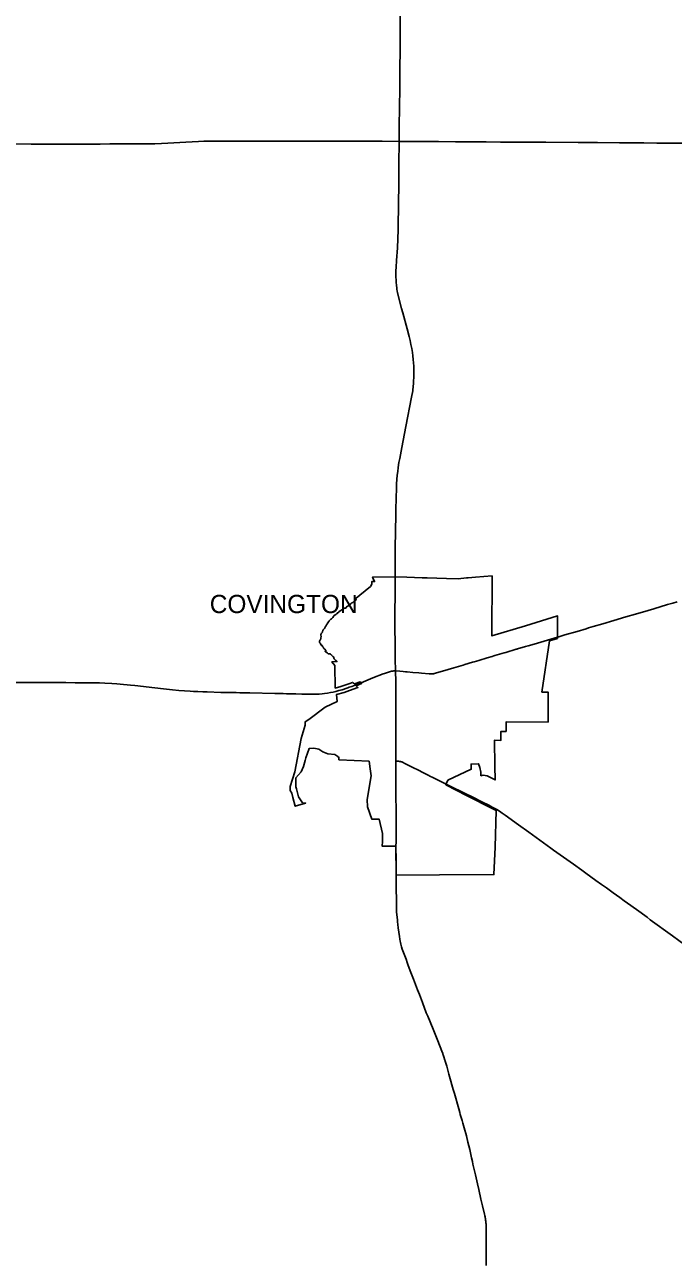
# Model space of a CAD drawing. Extents: x 0 to 34, y 0 to 22.
# Drawn here: x 4.445 to 4.73, y 17.041 to 17.585 of the extents above; entities that cross this region are included whole.
import ezdxf

# ---------------------------------------------------------------- set-up
doc = ezdxf.new("R2010")
doc.units = 0
for name, color, linetype in [('GM_X_Corporation', 7, 'Continuous'), ('GM_X_Corporation_Text', 7, 'Continuous'), ('GM_X_State_Route', 7, 'Continuous'), ('GM_X_US_Route', 7, 'Continuous')]:
    doc.layers.add(name, color=color, linetype=linetype)

msp = doc.modelspace()

# ---------------------------------------------------------------- linework, layer by layer
at = {"layer": 'GM_X_Corporation'}
msp.add_lwpolyline([(4.65031, 17.34146), (4.6502, 17.31741), (4.65023, 17.31588), (4.66507, 17.32035), (4.67914, 17.32467), (4.67914, 17.31535), (4.67907, 17.31474), (4.67565, 17.31371), (4.67228, 17.2911), (4.67507, 17.29106), (4.67497, 17.27792), (4.65652, 17.27798), (4.6565, 17.27383), (4.65425, 17.27383), (4.65423, 17.26987), (4.65139, 17.26991), (4.65139, 17.26991), (4.65158, 17.25847), (4.6517, 17.25246), (4.64813, 17.25421), (4.64639, 17.25453), (4.64542, 17.25427), (4.64538, 17.25584), (4.64487, 17.25795), (4.64442, 17.25955), (4.64106, 17.25939), (4.64115, 17.25716), (4.63092, 17.25232), (4.63009, 17.25066), (4.62993, 17.25032), (4.63944, 17.24537), (4.65036, 17.2399), (4.6521, 17.23892), (4.65169, 17.2228), (4.65117, 17.21077), (4.62721, 17.21059), (4.60809, 17.21046), (4.60802, 17.22326), (4.60191, 17.22332), (4.60204, 17.22525), (4.60212, 17.22889), (4.60067, 17.23512), (4.59741, 17.23509), (4.59548, 17.24061), (4.59538, 17.24379), (4.59619, 17.24901), (4.59664, 17.2518), (4.59709, 17.25426), (4.59667, 17.25727), (4.59619, 17.26065), (4.58301, 17.26132), (4.58291, 17.2613), (4.58287, 17.26247), (4.58247, 17.26255), (4.58247, 17.2627), (4.5811, 17.26367), (4.57806, 17.26399), (4.57582, 17.26474), (4.57408, 17.26596), (4.57193, 17.26642), (4.56988, 17.26628), (4.5684, 17.26214), (4.5681, 17.26106), (4.56737, 17.2583), (4.56635, 17.25601), (4.56396, 17.25335), (4.564, 17.24934), (4.5642, 17.2485), (4.56518, 17.24498), (4.56694, 17.24238), (4.56827, 17.24221), (4.56373, 17.24086), (4.5627, 17.24466), (4.56215, 17.24665), (4.56143, 17.2478), (4.56153, 17.24961), (4.56356, 17.25607), (4.56633, 17.27066), (4.56804, 17.27661), (4.56813, 17.27807), (4.56961, 17.2791), (4.57693, 17.28444), (4.58208, 17.28697), (4.58181, 17.29), (4.5853, 17.29097), (4.58758, 17.29176), (4.59125, 17.2932), (4.59048, 17.29394), (4.59293, 17.29489), (4.59262, 17.29526), (4.5922, 17.29566), (4.58973, 17.29469), (4.58896, 17.29542), (4.58731, 17.29476), (4.58556, 17.29411), (4.58379, 17.29353), (4.58131, 17.29286), (4.58111, 17.30289), (4.57986, 17.30449), (4.58203, 17.30455), (4.58199, 17.30468), (4.58176, 17.30485), (4.5816, 17.30496), (4.5814, 17.30513), (4.58128, 17.30531), (4.5808, 17.30572), (4.58071, 17.30602), (4.58062, 17.3064), (4.58047, 17.30668), (4.58024, 17.30686), (4.5801, 17.307), (4.57986, 17.30721), (4.57968, 17.30738), (4.57961, 17.30746), (4.57952, 17.30756), (4.57915, 17.30786), (4.57892, 17.30794), (4.57844, 17.30795), (4.57828, 17.308), (4.5782, 17.30804), (4.57788, 17.30825), (4.57774, 17.30848), (4.57757, 17.30865), (4.57745, 17.30868), (4.57717, 17.30875), (4.57694, 17.3089), (4.57683, 17.30904), (4.57694, 17.30921), (4.57709, 17.30934), (4.57709, 17.30952), (4.57704, 17.30964), (4.57684, 17.30985), (4.57674, 17.31004), (4.57665, 17.31005), (4.57645, 17.3102), (4.57632, 17.31035), (4.57617, 17.3105), (4.57608, 17.31071), (4.576, 17.31088), (4.57585, 17.31113), (4.57556, 17.31146), (4.57549, 17.31162), (4.57544, 17.31184), (4.57534, 17.31192), (4.57531, 17.31185), (4.57513, 17.31184), (4.57509, 17.31184), (4.57493, 17.31208), (4.57483, 17.31227), (4.57478, 17.31241), (4.57476, 17.31261), (4.5746, 17.31266), (4.57445, 17.31281), (4.57435, 17.31304), (4.57438, 17.31321), (4.57442, 17.31369), (4.57455, 17.31387), (4.57465, 17.31407), (4.5749, 17.31446), (4.57493, 17.31479), (4.57492, 17.31492), (4.57491, 17.31501), (4.57506, 17.31568), (4.57501, 17.31613), (4.57496, 17.31659), (4.57509, 17.31681), (4.57526, 17.31709), (4.57554, 17.31737), (4.57562, 17.31758), (4.57575, 17.31793), (4.57582, 17.31806), (4.57587, 17.31823), (4.57595, 17.31852), (4.57631, 17.31889), (4.57652, 17.31907), (4.57665, 17.31936), (4.57693, 17.31969), (4.57701, 17.32), (4.57708, 17.32008), (4.57716, 17.32022), (4.57725, 17.32045), (4.57739, 17.32069), (4.57753, 17.32094), (4.5778, 17.32125), (4.57828, 17.32201), (4.5785, 17.32224), (4.57861, 17.32253), (4.57901, 17.32291), (4.57923, 17.32312), (4.5794, 17.32328), (4.57968, 17.32343), (4.57977, 17.32356), (4.58022, 17.32399), (4.5805, 17.32444), (4.5807, 17.32467), (4.58087, 17.32482), (4.58113, 17.325), (4.58132, 17.32513), (4.58155, 17.32527), (4.58168, 17.32538), (4.58184, 17.32551), (4.58205, 17.32581), (4.58224, 17.32588), (4.58235, 17.32601), (4.58274, 17.32613), (4.58291, 17.32642), (4.58308, 17.32656), (4.58381, 17.32712), (4.58416, 17.3273), (4.58455, 17.32762), (4.58459, 17.32768), (4.58489, 17.32773), (4.58491, 17.32786), (4.58508, 17.32796), (4.58538, 17.32809), (4.58549, 17.32816), (4.58575, 17.32816), (4.58592, 17.32816), (4.58622, 17.32859), (4.58638, 17.32876), (4.58702, 17.32902), (4.58704, 17.3293), (4.5876, 17.32947), (4.58784, 17.32968), (4.58809, 17.32994), (4.58835, 17.33015), (4.58857, 17.33044), (4.58906, 17.33065), (4.58928, 17.33084), (4.58975, 17.33127), (4.59025, 17.33157), (4.59054, 17.3318), (4.59057, 17.33184), (4.5906, 17.33188), (4.58985, 17.33188), (4.59676, 17.33758), (4.59738, 17.33865), (4.59737, 17.33978), (4.59863, 17.33977), (4.59772, 17.34179), (4.60764, 17.34183), (4.61286, 17.3417), (4.61954, 17.34144), (4.6218, 17.34138), (4.63027, 17.34116), (4.63536, 17.34107), (4.63901, 17.34138), (4.63985, 17.34145), (4.64309, 17.34172), (4.65032, 17.34231)], close=True, dxfattribs=at)
at = {"layer": 'GM_X_State_Route'}
for p, q in [((4.6079, 17.28364), (4.60791, 17.28838)), ((4.60796, 17.27771), (4.60795, 17.27864)), ((4.60796, 17.27353), (4.60796, 17.27771)), ((4.608, 17.26346), (4.60798, 17.26847)), ((4.60802, 17.26073), (4.608, 17.26346))]:
    msp.add_line(p, q, dxfattribs=at)
for points in [[(4.60942, 17.5337), (4.60948, 17.53955), (4.60957, 17.54946), (4.60967, 17.55621), (4.60975, 17.56296), (4.60986, 17.57658), (4.60981, 17.58954)], [(4.43714, 17.53255), (4.44753, 17.5325), (4.45243, 17.53249), (4.45728, 17.53249), (4.46045, 17.53247), (4.46435, 17.53246), (4.47384, 17.5325), (4.4779, 17.53251), (4.48212, 17.53255), (4.49177, 17.53256), (4.49673, 17.53257), (4.49926, 17.53259), (4.50183, 17.53266), (4.5048, 17.53276), (4.50769, 17.53289), (4.51559, 17.53334), (4.52117, 17.53367), (4.52348, 17.53376), (4.52612, 17.53384), (4.53255, 17.53383), (4.54289, 17.53384), (4.54758, 17.5338), (4.55518, 17.53378), (4.5585, 17.53378), (4.5681, 17.53378), (4.57896, 17.53375), (4.58365, 17.53376), (4.59694, 17.53371), (4.60195, 17.53372), (4.60942, 17.5337)], [(4.60766, 17.34183), (4.60767, 17.34214), (4.60769, 17.34242), (4.60773, 17.35329), (4.60787, 17.36314), (4.60793, 17.36795), (4.60798, 17.37106), (4.6081, 17.37702), (4.60821, 17.38055), (4.60831, 17.38279), (4.60843, 17.38473), (4.60858, 17.38666), (4.60878, 17.38834), (4.609, 17.39001), (4.60934, 17.3922), (4.60966, 17.39402), (4.61059, 17.39883), (4.61242, 17.40805), (4.61493, 17.42102), (4.61538, 17.42385), (4.61547, 17.42452), (4.61556, 17.42531), (4.61563, 17.42606), (4.61569, 17.42673), (4.61578, 17.42809), (4.61586, 17.42988), (4.61589, 17.43167), (4.61588, 17.43309), (4.61584, 17.43462), (4.61575, 17.43614), (4.61563, 17.43761), (4.61546, 17.43918), (4.61525, 17.44069), (4.61495, 17.44251), (4.61463, 17.44422), (4.61424, 17.44602), (4.61382, 17.44776), (4.61295, 17.45108), (4.61103, 17.45821), (4.61052, 17.46015), (4.60906, 17.46576), (4.60874, 17.46719), (4.60862, 17.46778), (4.60847, 17.46862), (4.60837, 17.46937), (4.60829, 17.46999), (4.60822, 17.47059), (4.60817, 17.47118), (4.60806, 17.47266), (4.60801, 17.47382), (4.608, 17.47509), (4.60803, 17.47662), (4.60811, 17.47825), (4.6083, 17.4812), (4.6087, 17.48683), (4.60891, 17.49081), (4.60901, 17.49477), (4.60905, 17.49673), (4.60907, 17.49916), (4.60914, 17.50279), (4.60917, 17.50796), (4.60922, 17.51308), (4.60929, 17.5194), (4.6093, 17.52204), (4.60932, 17.52568), (4.60941, 17.53153), (4.60942, 17.5337)], [(4.60942, 17.5337), (4.6135, 17.53369), (4.61972, 17.53362), (4.62678, 17.53357), (4.63417, 17.53353), (4.6367, 17.5335), (4.64044, 17.53348), (4.64476, 17.53345), (4.64771, 17.53344), (4.65404, 17.53339), (4.65552, 17.53338), (4.65821, 17.53336), (4.66243, 17.53335), (4.66912, 17.53331), (4.67181, 17.5333), (4.67392, 17.53329), (4.68826, 17.53319), (4.69064, 17.53319), (4.69368, 17.53317), (4.69675, 17.53315), (4.7064, 17.53306), (4.71711, 17.533), (4.7229, 17.53297), (4.72533, 17.53294), (4.72955, 17.53292), (4.73708, 17.53284)], [(4.60785, 17.30055), (4.60772, 17.30581), (4.60769, 17.30686), (4.6077, 17.31117), (4.6077, 17.31133), (4.60762, 17.31549), (4.6076, 17.31643), (4.60757, 17.31849), (4.60757, 17.32036), (4.60756, 17.32165), (4.60756, 17.32249), (4.60757, 17.32509), (4.60757, 17.3258), (4.60758, 17.32659), (4.60763, 17.33375), (4.60762, 17.33534), (4.60764, 17.34152), (4.60766, 17.34183)], [(4.60791, 17.28838), (4.60792, 17.29567), (4.60785, 17.30055)], [(4.60795, 17.27864), (4.6079, 17.28357), (4.6079, 17.28364)], [(4.60798, 17.26847), (4.60796, 17.27197), (4.60796, 17.27353)], [(4.61038, 17.26043), (4.61009, 17.26051), (4.60979, 17.26056), (4.60958, 17.2606), (4.60921, 17.26064), (4.60802, 17.26073)], [(4.60805, 17.23673), (4.60805, 17.23877), (4.60805, 17.24036), (4.60803, 17.24415), (4.60804, 17.24822), (4.60804, 17.25069), (4.60803, 17.25533), (4.60802, 17.25861), (4.60802, 17.26073)], [(4.61952, 17.25587), (4.61817, 17.25655), (4.61765, 17.25681), (4.61575, 17.25774), (4.61317, 17.25907), (4.61191, 17.25972), (4.61091, 17.26023), (4.61066, 17.26034), (4.61038, 17.26043)], [(4.62958, 17.25088), (4.62395, 17.25364), (4.62323, 17.254), (4.62215, 17.25454), (4.61952, 17.25587)], [(4.73537, 17.17967), (4.72977, 17.18376), (4.71996, 17.19085), (4.71855, 17.19194), (4.71394, 17.19529), (4.70995, 17.19814), (4.70847, 17.19924), (4.70653, 17.20061), (4.70366, 17.20266), (4.70063, 17.20485), (4.69845, 17.20643), (4.696, 17.20818), (4.69155, 17.21138), (4.68986, 17.21263), (4.68612, 17.21529), (4.68321, 17.21739), (4.67739, 17.22157), (4.67619, 17.22243), (4.66652, 17.22939), (4.662, 17.23268), (4.65606, 17.23696), (4.65476, 17.23786), (4.65357, 17.23864), (4.65242, 17.23934), (4.6504, 17.24048), (4.64886, 17.24128), (4.64617, 17.24263), (4.6456, 17.24292), (4.64189, 17.24478), (4.63843, 17.24646), (4.6364, 17.24746), (4.63334, 17.24901), (4.63011, 17.25061), (4.62958, 17.25088)], [(4.60804, 17.22322), (4.60805, 17.2252), (4.60805, 17.23045), (4.60805, 17.23184), (4.60805, 17.23254), (4.60805, 17.23461), (4.60805, 17.23673)], [(4.60811, 17.21041), (4.60811, 17.21294), (4.6081, 17.217), (4.60804, 17.22322)], [(4.62202, 17.14843), (4.62139, 17.14988), (4.61974, 17.15435), (4.61832, 17.15795), (4.61754, 17.16003), (4.61621, 17.16352), (4.61573, 17.16475), (4.61461, 17.16765), (4.61389, 17.16958), (4.61328, 17.17121), (4.61296, 17.17205), (4.61246, 17.17343), (4.61132, 17.17644), (4.61081, 17.17788), (4.61046, 17.17898), (4.61032, 17.17949), (4.61016, 17.1801), (4.60999, 17.18079), (4.60988, 17.18141), (4.60974, 17.18227), (4.60956, 17.18347), (4.60907, 17.18733), (4.60889, 17.1888), (4.60875, 17.18989), (4.60865, 17.19073), (4.60836, 17.19322), (4.60829, 17.19412), (4.60826, 17.1946), (4.60823, 17.19502), (4.60821, 17.19649), (4.60814, 17.20752), (4.60811, 17.21041)], [(4.64775, 17.03856), (4.64775, 17.0414), (4.64775, 17.04175), (4.64774, 17.04341), (4.6478, 17.05364), (4.64776, 17.05548), (4.64774, 17.05581), (4.64773, 17.05616), (4.64771, 17.05653), (4.64767, 17.05693), (4.64765, 17.05726), (4.64759, 17.05772), (4.64754, 17.05815), (4.64749, 17.05846), (4.64742, 17.05891), (4.64738, 17.05919), (4.64731, 17.05953), (4.64723, 17.05999), (4.64715, 17.06038), (4.64709, 17.06065), (4.64699, 17.0611), (4.64614, 17.0648), (4.64544, 17.06778), (4.64447, 17.07204), (4.64391, 17.07456), (4.643, 17.07852), (4.64191, 17.08314), (4.64165, 17.08438), (4.6413, 17.08603), (4.64049, 17.08963), (4.6401, 17.09132), (4.63973, 17.09281), (4.63901, 17.09567), (4.63806, 17.09913), (4.63745, 17.10131), (4.63716, 17.10238), (4.63663, 17.10415), (4.63634, 17.10511), (4.63611, 17.10596), (4.63565, 17.10759), (4.63372, 17.11439), (4.63324, 17.11607), (4.63293, 17.11718), (4.63192, 17.12078), (4.63132, 17.12286), (4.63036, 17.12632), (4.62971, 17.12855), (4.62964, 17.12879), (4.62955, 17.12907), (4.62909, 17.1305), (4.62895, 17.13093), (4.62883, 17.1313), (4.62873, 17.1316), (4.62861, 17.13192), (4.62821, 17.13303), (4.62643, 17.13758), (4.62437, 17.14264), (4.62202, 17.14843)]]:
    msp.add_lwpolyline(points, dxfattribs=at)
at = {"layer": 'GM_X_US_Route'}
for points in [[(4.67924, 17.31533), (4.68239, 17.31629), (4.6878, 17.31788), (4.69169, 17.31905), (4.69279, 17.31936), (4.69488, 17.31997), (4.69908, 17.32121), (4.70394, 17.32263), (4.70925, 17.32421), (4.7135, 17.32545), (4.71896, 17.32708), (4.72158, 17.32786), (4.72755, 17.32963), (4.72992, 17.33035), (4.73174, 17.33088)], [(4.65151, 17.30718), (4.65562, 17.3084), (4.65634, 17.30861), (4.66099, 17.30997), (4.66129, 17.31006), (4.66146, 17.31011), (4.665, 17.31115), (4.66625, 17.31152), (4.66886, 17.31229), (4.6733, 17.31361), (4.67916, 17.3153), (4.67924, 17.31533)], [(4.61216, 17.30007), (4.61284, 17.3), (4.61298, 17.29999), (4.61542, 17.29979), (4.6181, 17.29958), (4.61927, 17.29949), (4.62261, 17.29922), (4.62356, 17.29917), (4.62408, 17.29917), (4.62432, 17.29919), (4.62454, 17.29922), (4.62478, 17.29926), (4.625, 17.2993), (4.62592, 17.29955), (4.62852, 17.30032), (4.63355, 17.30181), (4.63754, 17.30299), (4.63835, 17.30323), (4.64174, 17.30423), (4.64241, 17.30443), (4.64449, 17.30506), (4.64811, 17.30615), (4.65042, 17.30685), (4.65111, 17.30706), (4.65151, 17.30718)], [(4.58156, 17.29142), (4.58283, 17.29176), (4.58366, 17.29198), (4.58429, 17.29216), (4.58485, 17.29233), (4.5859, 17.29268), (4.58681, 17.29299), (4.58749, 17.29323), (4.58862, 17.29365), (4.59014, 17.29424), (4.59132, 17.29469), (4.59264, 17.29521), (4.59789, 17.29735), (4.60245, 17.29916), (4.60291, 17.29932), (4.60513, 17.29998)], [(4.60513, 17.29998), (4.60611, 17.30028), (4.60663, 17.3004), (4.60708, 17.30049), (4.60753, 17.30054), (4.60785, 17.30055)], [(4.60785, 17.30055), (4.6098, 17.30034), (4.61115, 17.30018), (4.61216, 17.30007)], [(4.43714, 17.29533), (4.44482, 17.29532), (4.44767, 17.29531), (4.45548, 17.29528), (4.4627, 17.2953), (4.46687, 17.29527), (4.47367, 17.29523), (4.47749, 17.29516), (4.47983, 17.29506), (4.48295, 17.2949), (4.48521, 17.29475), (4.48663, 17.29463), (4.49115, 17.29423), (4.49309, 17.29402), (4.50184, 17.29298), (4.50566, 17.29255), (4.5096, 17.29215), (4.51249, 17.29188), (4.51501, 17.2917), (4.51741, 17.29153), (4.51895, 17.29144), (4.52083, 17.29137), (4.52295, 17.29128), (4.52491, 17.29119), (4.53097, 17.291), (4.53461, 17.29091), (4.53766, 17.29088), (4.53938, 17.29085), (4.54367, 17.29074), (4.55469, 17.2905), (4.55838, 17.29045), (4.55991, 17.29041), (4.56402, 17.2903), (4.56655, 17.29024), (4.56908, 17.2902), (4.5705, 17.29016), (4.57171, 17.29016), (4.57277, 17.29019), (4.57419, 17.29027), (4.5755, 17.29037), (4.57654, 17.29049), (4.57785, 17.29067), (4.5792, 17.29091), (4.58038, 17.29115), (4.58156, 17.29142)]]:
    msp.add_lwpolyline(points, dxfattribs=at)

# ---------------------------------------------------------------- texts
at = {"layer": 'GM_X_Corporation_Text'}
msp.add_text('COVINGTON', height=0.008037, rotation=0, dxfattribs=at).set_placement((4.52607, 17.32591))

doc.saveas('drawing.dxf')
